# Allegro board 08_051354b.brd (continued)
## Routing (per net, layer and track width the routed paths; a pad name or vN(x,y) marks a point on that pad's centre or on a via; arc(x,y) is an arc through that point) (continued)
UNNAMED_5_ADP5023_I567_FB1: length 4.7
  TOP w0.305: v1(17.57,10.92) 17.57,9.97 17.7,9.84 R30.1 R23.1
  BOTTOM w0.203: v1(17.57,10.92) 18.21,11.55 U3.11
UNNAMED_5_ADP5023_I567_FB2: length 7.6
  TOP w0.305: v1(20.83,11.23) 20.83,10.67 20.16,10 v1(20.16,8.58)
  BOTTOM w0.203: R21.1 R20.1 19.35,8.17 19.75,8.58 v1(20.16,8.58)
  BOTTOM w0.305: v1(20.83,11.23) 20.06,11.23 19.71,11.58 U3.8
UNNAMED_5_ADP5023_I567_FB3: length 6.6
  TOP w0.203: v1(17.45,17.14) 17.09,16.79 14.38,16.79 14.01,17.15 R19.1 R18.2
  BOTTOM w0.254: v1(17.45,17.14) 17.71,16.88 U3.19
UNNAMED_5_ADP5023_I567_MODE: length 3.2
  BOTTOM w0.203: U3.13 16.38,12.91 15.54,12.06 15.54,10.79 JP4.2
UNNAMED_5_ADP5023_I567_SW1: length 4.5
  BOTTOM w0.254: 12.53,13.92 15.1,13.92 15.15,13.97 15.24,13.97 15.75,13.97 15.81,13.91 U3.15
UNNAMED_5_ADP5023_I567_SW2: length 3.6
  BOTTOM w0.254: U3.4 24.57,13.91
UNNAMED_5_ADP5023_I567_VOUT1: length 9.4
  TOP w0.508: R22.1 20.06,7.4 18.95,8.51 v1(18.63,8.51) 18.02,7.91 R30.2
  BOTTOM w0.254: 18.71,10.83 18.72,10.84 ; 18.71,10.83 U3.10 ; 18.71,10.83 18.41,10.54
UNNAMED_5_ADP5023_I567_VOUT2: length 13.1
  BOTTOM w0.305: U3.9 19.21,10.05 19.6,9.65 ; 26.44,10.18 26.44,10.27 C47.1 26.5,10.25 26.44,10.18 ; 26.44,10.18 26.44,9.14 26.14,8.84 23.83,8.84 23.37,8.38 23.37,7.75 22.11,6.48 R21.2 20.49,5.34 R32.1
UNNAMED_5_ADP5023_I567_VOUT3: length 1.2
  BOTTOM w0.254: U3.20 18.21,17.35
  vias: v1(17.11,17.97) v1(17.79,17.97)
UNNAMED_5_ADP5071_I420_COMP1: length 2.1
  TOP w0.203: R50.1 26.54,24.38 25.89,23.73 U10.6
UNNAMED_5_ADP5071_I420_COMP2: length 1.9
  TOP w0.203: R51.1 23.29,24.61 23.89,24 U10.10
UNNAMED_5_ADP5071_I420_EN1: length 6.1
  TOP w0.203: U10.7 25.39,24.18 25.7,24.49 25.7,25.51 v1(25.71,25.53)
  BOTTOM w0.203: JP7.2 23.29,25.26 24.04,26.01 25.22,26.01 25.7,25.53 v1(25.71,25.53)
UNNAMED_5_ADP5071_I420_EN2: length 10.3
  TOP w0.203: U10.9 24.39,24.04 25.19,24.84 25.19,26.24 25.77,26.82 29.23,26.82 v1(30.35,25.69)
  BOTTOM w0.203: v1(30.35,25.69) 30.35,25.65 30.39,25.62 JP6.2
UNNAMED_5_ADP5071_I420_FB1: length 4.6
  TOP w0.203: R48.1 29.89,23.38 ; 29.89,23.38 R52.1 ; 29.89,23.38 29.88,23.39 28.69,23.39 27.6,22.31 U10.5
UNNAMED_5_ADP5071_I420_FB2: length 6.2
  TOP w0.305: U10.11 21.55,22.31 21.13,22.73 21.13,24.01 20.23,24.9 R46.2 R49.1
UNNAMED_5_ADP5071_I420_INBK: length 4.4
  TOP w0.305: L9.1 30.84,20.87 30.28,20.31 U10.1
UNNAMED_5_ADP5071_I420_PVIN1: length 11.7
  TOP w0.254: 24.19,17.22 24.39,17.42 U10.17
  TOP w0.305: C41.1 23.89,16.24 U10.16 ; U10.15 21.92,20.31 20.42,18.82 20.42,16.89 20.68,16.64 21.21,16.64
UNNAMED_5_ADP5071_I420_SW2: length 1.5
  TOP w0.305: U10.18 24.89,17.83
UNNAMED_5_ADP5071_I420_SYNC: length 9.9
  TOP w0.203: U10.2 27.48,20.81 27.74,21.08 27.74,21.85 28.49,22.61 v1(31.82,22.61)
  BOTTOM w0.203: JP8.2 34.21,22.81 34.01,22.61 v1(31.82,22.61)
UNNAMED_5_ADP5071_I420_VREF: length 6.4
  TOP w0.305: R46.1 19.23,24.99 20.15,24.07 C43.1 20.32,22.46 20.38,22.46 21.05,21.79 22.86,21.79 U10.12
UNNAMED_5_ADP5071_I420_VREG: length 3
  TOP w0.305: U10.14 22.86,20.79 21.6,20.79 20.85,20.04 C66.1
UNNAMED_5_ADP7112_I458_EN: length 4.2
  TOP w0.203: U12.C1 102.12,10.61 v1(102.12,11.18)
  BOTTOM w0.203: R38.1 102.13,11.18 v1(102.12,11.18) 101.61,10.67 JP9.2
UNNAMED_5_ADP7112_I458_SENSE: length 5.4
  TOP w0.203: 100.98,10.24 101.18,10.03 U12.B2
  TOP w0.305: R57.1 97.51,9.84 R58.1 97.97,10.29 100.93,10.29 100.98,10.24
UNNAMED_5_ADP7112_I458_SS: length 2.7
  TOP w0.203: U12.B1 102.5,10.03 102.88,10.41 v1(103.52,10.41)
  BOTTOM w0.203: v1(103.52,10.41) 103.78,10.68 C80.1
UNNAMED_5_ADP7112_I458_VIN: length 4.1
  TOP w0.203: U12.A1 102.38,9.2
  TOP w0.508: 102.67,8.89 C79.1 104.03,7.73 ; R56.2 106.06,8.09
UNNAMED_5_ADP7112_I458_VOUT: length 6.1
  TOP w0.203: U12.A2 101.18,9.27
  TOP w0.508: C81.1 99.45,7.75 ; C81.1 100.81,8.89 ; C81.1 97.58,8.89 R58.2 97.51,7.82 R59.1
UNNAMED_5_CAP_I499_N1: length 21.5
  TOP w0.305: R49.2 18.47,26.67 18.16,26.37 v1(18.16,25.15)
  L3_SIG w0.305: v1(21.46,8.76) 21.05,8.76 20.24,9.57 20.24,15.77 21.05,16.58 21.05,23.02 18.92,25.15 v1(18.16,25.15)
UNNAMED_5_CAP_I500_N1: length 17
  TOP w0.203: R52.2 v1(31.8,23.37)
  TOP w0.508: 32.01,13.21 32.51,13.21 33.02,12.7 v1(33.02,11.69)
  L3_SIG w0.305: v1(31.8,23.37) 31.92,23.37 34.97,20.32 34.97,13.64 v1(33.02,11.69)
UNNAMED_5_CAP_I511_N1: length 16.4
  BOTTOM w0.508: 8.47,28.3 C42.1 ; C42.1 9.86,27.4 ; C42.1 9.86,29.2 ; C42.1 11.24,28.3 ; 7.27,28.62 E2.1 ; E2.1 7.27,30.78 ; E2.1 8.22,29.7 ; R100.2 8.02,32.14 ; R100.2 7.27,31.29 ; R100.2 7.27,32.99 ; S2.2 14.28,26.54 ; S2.2 11.12,26.54 ; S2.2 12.7,28.12 ; S2.2 12.7,24.97
UNNAMED_5_CAP_I516_N1: length 1.1
  TOP w0.203: R50.2 C72.1
UNNAMED_5_CAP_I517_N1: length 1.1
  TOP w0.305: R51.2 C74.1
UNNAMED_5_CN4PV6_I401_N1: length 21.8
  TOP w0.508: 3.06,3.63 P31.1B ; P31.1B 4.62,5.38 ; P31.1B 3.06,7.13 ; D1.C 7.23,19.06 ; D1.C 8.48,17.62 ; D1.C 5.99,17.62 ; D1.C 7.23,16.18 ; 3.06,9.73 P31.1A ; P31.1A 4.62,11.48 ; P31.1A 3.06,13.23 ; 12.7,20.27 S2.1 ; S2.1 11.12,21.84 ; S2.1 12.7,23.42 ; S2.1 14.28,21.84
UNNAMED_5_DIOLED_I652_P: length 5.7
  TOP w0.508: DS1.A 7.81,34.66 v1(6.77,34.66)
  BOTTOM w0.508: v1(6.77,34.66) 5.57,33.46 R100.1
UNNAMED_5_DIOLED_I662_P: length 2.4
  TOP w0.508: DS2.A v1(7.8,39.12)
  BOTTOM w0.508: R104.2 v1(7.8,39.12)
UNNAMED_5_DIOLED_I665_P: length 2.7
  TOP w0.508: DS3.A v1(7.67,42.42)
  BOTTOM w0.508: R108.1 v1(7.67,42.42)
UNNAMED_7_ADA4800PRELIM_I10_IDR: length 3.1
  TOP w0.203: C65.1 R33.1 111.55,20.45 111.55,21.08 112.21,21.73 A1.4
UNNAMED_7_ADA4800PRELIM_I10_IN: length 13.2
  TOP w0.203: U1.21 99.73,20.56 102.28,23.11 109.73,23.11 109.86,22.98 A1.1
UNNAMED_7_ADA4800PRELIM_I10_ISF: length 3.7
  TOP w0.203: A1.6 112.82,22.98 113.47,23.63 R31.1 C29.2
UNNAMED_7_ADA4800PRELIM_I10_OUT: length 1.6
  TOP w0.254: A1.3 109.75,21.98 109.48,21.71 R76.1
UNNAMED_7_ADA4800PRELIM_I10_VPO: length 2.9
  TOP w0.254: 112.97,22.34 112.97,21.48 112.56,21.07 R33.2 ; A1.5 113.03,22.48
UNNAMED_7_CAP_I99_N1: length 6.8
  BOTTOM w0.203: R27.1 C30.1 108.62,28.61 107.77,27.76 D5.A 108.38,27.15 108.82,26.72 Q1.3 109.56,26.72 109.73,26.54 109.73,26.16 109.58,26.02 Q1.1
UNNAMED_7_CAP_I107_N1: length 3.2
  BOTTOM w0.203: R7.2 C18.1 108.4,25.85 108.91,26.36 109.28,26.36 109.28,26.37 Q1.2
UNNAMED_7_CAP_I131_N1: length 2.1
  TOP w0.254: U1.30 99.21,26.78
  TOP w0.381: U1.30 v5(98.24,27.94)
  vias: v5(99.19,27.94)
UNNAMED_7_CAP_I133_N1: length 0.5
  BOTTOM w0.203: R69.2 C73.1
UNNAMED_7_CAP_I133_N2: length 5.2
  TOP w0.203: v1(97.2,21.86) U1.23
  BOTTOM w0.203: C73.2 96.38,25.08 97.2,24.26 v1(97.2,21.86)
UNNAMED_7_CAP_I142_N1: length 2
  TOP w0.406: U1.19 97.11,20.8 v1(96.57,21.34)
UNNAMED_7_CAP_I150_N1: length 3
  TOP w0.203: C21.1 110.49,19.38 JP5.1 R76.2
UNNAMED_7_ICFAN3121_I89_EN: length 11.3
  BOTTOM w0.203: JP2.2 95.63,12.32 98.11,14.8 102.35,14.8 102.66,15.11 102.66,15.78 102.46,15.98 U6.3
UNNAMED_7_ICFAN3121_I89_IN: length 4.2
  BOTTOM w0.203: U6.2 102.54,16.63 103.04,16.13 103.04,14.68 102.52,14.16 R5.2
UNNAMED_7_MN34906BL_I91_HL: length 7.1
  TOP w0.203: U1.17 v1(95.81,20.7)
  BOTTOM w0.203: R66.2 91.33,22.01 92.65,20.7 v1(95.81,20.7)
UNNAMED_7_RES_I93_N2: length 1.4
  BOTTOM w0.203: Q1.5 Q1.6 111.3,26.02 R26.2
UNNAMED_10_ADDI9036_I362_AUXINA: length 24.6
  TOP w0.203: RT1.2 69.06,32.62 R72.1 ; RT1.2 70.37,31.61 70.74,31.24 v1(71.37,31.24) ; RT1.2 70.65,32.9 R73.2 C57.2
  L2_GND w0.14: v4(74.4,22.91) 74.9,23.41 v2(74.9,23.41)
  L3_SIG w0.165: v1(71.37,31.24) 69.93,31.24 66.92,28.22 66.92,25.38 67.23,25.07 67.23,24.22 67.45,24 67.98,24 68.09,24.11 70.46,24.11 70.97,23.6 72.33,23.6 72.51,23.41 73.9,23.41 v4(74.4,22.91)
UNNAMED_10_ADDI9036_I362_DNC3: length 11.5
  TOP w0.14: 72.32,15.65 73.07,16.4 v2(73.07,18.71)
  TOP w0.203: 72.32,15.65 71.28,15.65 70.84,15.22 70.84,14.07 70.16,13.39 R89.1
  L2_GND w0.14: v2(73.07,18.71) 73.07,18.97 74.73,20.62 74.73,21.23 v2(74.9,21.41)
UNNAMED_10_ADDI9036_I362_DNC4: length 33
  L3_SIG w0.165: v1(68.24,20.32) 68.24,19.83 68.91,19.16 70.45,19.16 70.73,19.45 70.73,19.86 71.02,20.16 73.28,20.16 75.04,21.91 v4(75.4,21.91)
  L8_SIG w0.203: v1(64.52,28.7) 67.23,25.99 67.23,22.96 68.24,21.95 v1(68.24,20.32)
  BOTTOM w0.203: R88.1 75.64,26.25 75.44,26.45 75.44,27.94 74.81,28.57 73.53,28.57 73.28,28.32 69.23,28.32 68.85,28.7 v1(64.52,28.7)
UNNAMED_10_ADDI9036_I362_I2CSCL: length 20.5
  L3_SIG w0.165: v4(75.9,22.41) 75.9,23.08 75.56,23.42 75.56,27.26 75.4,27.42 73.76,27.42 73.17,28.02 70.79,28.02 v1(70.51,27.74)
  BOTTOM w0.203: v1(70.51,27.74) 70.51,26.7 70.94,26.26 71.53,26.26 71.83,25.96 71.83,23.37 73.57,21.63 R28.2 R41.2
UNNAMED_10_ADDI9036_I362_I2CSDA: length 7.9
  L3_SIG w0.122: 74.83,25.92 74.83,25.65 75.26,25.22 75.26,23.19 75.4,23.05 v4(75.4,22.41)
  L3_SIG w0.165: v3(74.83,26.44) 74.83,25.92
  BOTTOM w0.203: R6.2 R3.2 75.34,25.06 74.83,25.58 v3(74.83,26.44)
UNNAMED_10_ADDI9036_I362_MTEST: length 8.3
  L2_GND w0.14: 78.74,19.68 78.55,19.87 78.1,19.87 77.97,20 77.97,20.84 v2(77.4,21.41)
  L2_GND w0.203: v1(80.17,18.01) 78.91,19.27 78.91,19.51 78.74,19.68
  BOTTOM w0.203: R2.2 79.99,20.95 79.99,18.7 80.17,18.52 v1(80.17,18.01)
UNNAMED_10_FERRITE_I381_N1: length 5
  TOP w0.203: E1.1 66.41,27.21 C5.1 64.3,28.22 R1.2 63.65,26.95 Y1.4
UNNAMED_10_ICAT24CM01_I285_A2: length 3.7
  BOTTOM w0.203: U5.3 45.42,16.81 R47.1 R54.2
UNNAMED_10_ICAT24CM01_I285_WP: length 4.1
  BOTTOM w0.203: U5.7 46.07,26.75 R55.1 R60.2
UNNAMED_10_RES_I124_N1: length 1.6
  TOP w0.203: Y1.1 62.65,26.95 R1.1
UNNAMED_10_RES_I290_N1: length 3.5
  BOTTOM w0.203: R63.2 R62.1 46.25,17.02 46.07,17.21 U5.2
UNNAMED_10_RES_I374_N1: length 1.5
  TOP w0.203: R110.1 63.86,23.94 63.87,23.94 Y1.3
UNNAMED_12_ADT7410_I24_A0: length 4.4
  TOP w0.203: v1(92.22,10.54) 91.33,10.54 R106.2 91.07,10.54 U13.3
  BOTTOM w0.203: v1(92.22,10.54) 91.33,10.54 R106.2
UNNAMED_12_ADT7410_I24_A1: length 4.4
  TOP w0.203: U13.4 91.07,11.81 R103.2 91.33,11.81 v1(92.22,11.81)
  BOTTOM w0.203: R103.2 91.33,11.81 v1(92.22,11.81)
UNNAMED_12_CAP_I106_N2: length 7.5
  TOP w0.229: E5.2 76.94,7.96
  TOP w0.305: v1(73.66,9.47) 74.16,8.97 74.16,8.1 C1.2 74.86,7.6 75.54,8.27 C56.2 76.37,8.27 76.68,7.96 76.94,7.96
  BOTTOM w0.203: U7.10 73.86,9.97 73.66,9.78 v1(73.66,9.47)
UNNAMED_12_CN30PV2_I137_N13: length 13.4
  TOP w0.203: R98.2 v1(40.03,22.71) ; v1(48.48,26.61) 48.09,27 P1.13
  L3_SIG w0.165: v1(40.03,22.71) 40.74,22 42.13,22 47.12,26.98 47.92,26.98 47.94,26.96 48.13,26.96 v1(48.48,26.61)
UNNAMED_12_CN30PV2_I137_N14: length 13.1
  TOP w0.203: v1(40.95,22.73) 40.95,22.25 R109.2 ; v1(48.99,27.63) 48.61,28 P1.14
  L3_SIG w0.165: v1(48.99,27.63) 48.5,27.63 48.4,27.53 46.98,27.53 42.18,22.73 v1(40.95,22.73)
UNNAMED_12_CN30PV2_I137_N15: length 11.9
  TOP w0.508: v1(45.33,30.06) 45.33,29.3 45.63,29 P1.15
  L8_SIG w0.508: v1(49.66,23.31) 47.32,25.64 47.32,27.4 45.33,29.4 v1(45.33,30.06)
  BOTTOM w0.508: v1(49.66,23.31) 49.66,23.89 R35.2
UNNAMED_12_CN40PV2_I59_N15: length 89.9
  TOP w0.305: S3.2 38.64,3.98 38.04,4.58 C84.1 v1(36.96,5.71)
  L3_SIG w0.165: v1(67.55,39.24) 67.55,39.66 64.73,42.48 39.46,42.48 38.31,43.63 28.99,43.63 27.05,41.69 v1(27.05,41.4)
  L8_SIG w0.203: v1(27.05,41.4) 26.42,40.77 26.42,22.86 36.96,12.32 v1(36.96,5.71)
  BOTTOM w0.203: P4.29 v1(67.55,39.24)
UNNAMED_12_CN40PV2_I60_N14: length 89.6
  TOP w0.305: S4.1 41.24,3.98 41.85,4.58 C85.1 v1(42.67,5.71)
  L3_SIG w0.165: v1(28.11,41.23) 30.04,43.16 37.75,43.16 38.92,41.99 63.96,41.99 65.55,40.39 v1(65.55,39.88)
  L8_SIG w0.203: v1(42.67,5.71) 42.9,5.71 43.1,5.92 43.1,6.69 42.68,7.11 40.77,7.11 37.85,10.03 37.85,12.53 27.05,23.32 27.05,40.17 v1(28.11,41.23)
  BOTTOM w0.203: P4.28 v1(65.55,39.88)
UNNAMED_12_CN60PODDEVEN_I121_N5: length 2.5
  TOP w0.203: R113.2 53.43,3.8 v1(53.89,4.26)
  BOTTOM w0.203: v1(53.89,4.26) P3.9
UNNAMED_12_DIOLED_I181_N: length 55
  TOP w0.203: DS4.C v1(38.9,6.44) ; v1(14.82,39.5) 14.88,39.56 Q2.6
  L8_SIG w0.203: v1(14.82,39.5) 14.82,39.12 14.82,35.85 17.53,33.15 17.53,25.04 21.34,21.23 21.34,17.27 24.77,13.84 24.77,9.14 29.84,4.06 30.63,4.06 31.15,3.54 31.58,3.54 32.11,4.06 37.97,4.06 38.9,4.99 v1(38.9,6.44)
UNNAMED_12_DIOLED_I181_P: length 1.7
  TOP w0.305: R37.1 37.3,9.09 DS4.A
UNNAMED_12_DIOLED_I182_N: length 54.4
  TOP w0.203: DS5.C v1(42.58,6.48) ; Q2.3 v1(18.03,37.66)
  L8_SIG w0.203: v1(42.58,6.48) 40.39,6.48 39.75,7.11 38.35,7.11 37.85,6.6 37.85,5.46 37.21,4.83 30.35,4.83 25.53,9.65 25.53,17.88 18.68,24.73 18.68,33.01 17.65,34.04 17.65,37.28 v1(18.03,37.66)
UNNAMED_12_DIOLED_I182_P: length 1.7
  TOP w0.305: DS5.A 40.98,9.09 R75.2
UNNAMED_12_ICFSA642_I1_OEN: length 2.4
  BOTTOM w0.203: R90.2 76.04,10.11 75.92,9.99 74.92,9.99 74.65,10.25 U7.8
UNNAMED_12_ICFSA642_I1_SEL: length 103.4
  TOP w0.203: v1(5.88,38.52) S1.2
  L3_SIG w0.305: v1(5.88,38.52) 8.72,35.68 8.72,28.19 14.34,22.57 14.34,11.72 20.03,6.04 28.79,6.04 30.1,4.73 35.08,4.73 38.73,8.38 50.42,8.38 51.94,9.91 60.07,9.91 62.1,11.94 65.08,11.94 65.38,11.63 65.38,10.32 65.02,9.96 65.02,7.88 65.43,7.47 72.38,7.47 72.87,7.97 72.87,9.31 v1(72.99,9.42)
  BOTTOM w0.203: v1(72.99,9.42) 73.05,9.48 73.05,9.79 73.46,10.2 U7.11
UNNAMED_12_ICPCA9517A_I144_EN: length 2.7
  TOP w0.203: R101.1 88.66,38.1 87.86,38.9 U8.5
UNNAMED_12_ICPCA9517A_I145_EN: length 3.6
  BOTTOM w0.203: R24.2 76.34,33.78 75.79,33.23 U9.5
UNNAMED_12_RES_I54_N1: length 2.9
  TOP w0.203: S1.1 2.92,41.27 3.13,41.49 R91.1
UNNAMED_12_RES_I55_N2: length 2.1
  TOP w0.203: R36.2 2.29,37.47 S1.3
UNNAMED_12_RES_I155_N2: length 2.1
  TOP w0.508: S3.1 32.74,2.42 R77.2
UNNAMED_12_RES_I158_N2: length 2.1
  TOP w0.508: S4.2 47.14,2.42 R80.2
UNNAMED_12_RES_I178_N2: length 2.2
  TOP w0.203: R78.2 16.38,36.66 Q2.2
UNNAMED_12_RES_I179_N2: length 2
  TOP w0.203: R79.2 16.38,40.55 Q2.5
VD: length 59.1
  TOP w0.14: v1(77.82,15.54) 77.59,15.77 76.53,15.77 75.99,16.31 75.99,18.97 75.4,19.56 U4.F1
  TOP w0.203: TP1.1 47.29,39.95 47.77,39.95 47.8,39.91 53.59,39.91 53.9,39.6 v1(57.88,39.6)
  L8_SIG w0.165: v1(57.88,39.6) 60.72,36.76 63.04,36.76 64.65,35.15 64.65,31.75 63.5,30.6 63.5,27.05 64.65,25.9 64.65,22.97 65.03,22.59 65.03,21.18 66.21,20 67.85,20 68.03,19.82 68.45,19.82 68.83,20.2 76.33,20.2 78.21,18.31 78.21,15.94 v1(77.82,15.54)
VL: length 1.2
  TOP w0.508: R10.1 83.53,28.48 v1(84.15,28.48)
  vias: v5(27.14,3.11) v5(27.52,2.35) v5(28.32,3.08) v5(28.92,2.35) v5(29.43,3.11) v5(102.87,36.32) v5(102.87,35.43)
VL_AFE: length 7
  TOP w0.203: 77.6,25.91 77.4,25.71 U4.K11
  TOP w0.305: 77.6,25.91 78.03,26.34 79.52,26.34 79.71,26.53 C27.1
  TOP w0.508: C27.1 81.36,26.53 C20.2 81.44,26.81 R10.2
VLD: length 19.1
  TOP w0.254: P21.12 59.41,27.67 ; P21.10 59.41,28.17 ; P21.14 59.41,27.17 ; P21.18 59.41,26.17 ; P21.22 59.41,25.17 ; P21.8 59.41,28.67 ; P21.4 59.41,29.67 ; P21.2 59.41,30.18 ; P21.6 59.41,29.17 ; P21.16 59.41,26.67 ; P21.20 59.41,25.67 ; P21.24 59.41,24.67
  BOTTOM w0.508: R108.2 v1(10.76,41.27)
  vias: v1(59.56,30.1) v1(59.56,28.57) v1(59.56,27.81) v1(59.56,27.05) v1(59.56,26.29) v1(59.65,29.34) v1(59.75,25.07) v1(60.24,27.12) v1(60.33,29.21) v5(29.97,33.02) v5(29.97,32.13) v5(30.78,33.02) v5(30.78,32.13) v5(31.62,33.02) v5(31.62,32.13) v5(31.62,31.29) v5(31.62,30.48) v5(32.44,33.02) v5(32.44,32.13) v5(32.44,31.29) v5(32.44,30.48) v5(36.56,32.61) v5(36.56,31.6) v5(37.45,32.61) v5(37.45,31.6) v5(38.27,32.64) v5(38.27,31.62) v5(39.12,32.64) v5(39.12,31.62)
VSUB: length 8.3
  TOP w0.508: v5(106.06,11.56) R56.1
  BOTTOM w0.305: U6.8 98.49,17.28 98.07,17.7 v5(98.07,17.89)
  BOTTOM w0.381: v1(101.22,12.57) 100.71,12.57 100.31,12.17 100.31,10.82 100.78,10.35 JP9.1
  BOTTOM w0.508: JP2.1 v5(94.79,12.06)
  vias: v5(29.72,8.13) v5(29.72,6.86) v5(30.61,8.13) v5(30.61,6.86) v5(104.52,14.35) v5(104.57,17.68) v5(105.54,14.61) v5(105.58,20.73) v5(105.58,19.71) v5(105.58,18.69) v5(105.58,17.68) v5(105.58,16.66) v5(105.58,15.65)

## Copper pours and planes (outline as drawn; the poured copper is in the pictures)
5V_LD on TOP: 50.16,20.45 50.16,23.88 50.85,23.88 50.85,23.8 52.18,23.8 52.31,23.67 52.18,23.54 50.85,23.54 50.85,23.3 52.18,23.3 52.31,23.17 52.18,23.04 50.85,23.04 50.85,22.8 52.18,22.8 52.31,22.67 52.18,22.54 50.85,22.54 50.85,22.3 52.18,22.3 52.31,22.17 52.18,22.04 50.85,22.04 50.85,21.8 52.18,21.8 52.31,21.67 52.18,21.54 50.85,21.54 50.85,21.3 52.18,21.3 52.31,21.17 52.18,21.04 50.85,21.04 50.85,20.79 52.18,20.79 52.31,20.67 52.18,20.54 50.85,20.54 50.85,20.45
5V_LD on BOTTOM: 7.46,23.69 7.11,23.37 7.11,21.34 7.33,21.15 9.49,21.15 10,21.66 10,23.43 9.74,23.69
5V_LD on BOTTOM: 16.91,29.84 16.91,31.78 16.4,32.28 14.67,32.28 14.42,32.03 14.42,30.02 14.6,29.84
5V_LD on BOTTOM: 34.87,27.71 34.87,25.32 39.8,25.32 39.8,27.71
5V_LD on L5_PWR: 1.27,17.08 1.27,34.35 26.41,34.35 28,32.76 28,29.97 29.33,28.64 51.18,28.64 52.01,27.81 52.01,20.58 51.43,20 21.21,20 20.51,20.71 20.51,23.63 18.8,25.34 14.09,25.34 12.13,23.37 12.13,20.2 9.01,17.08
5VCC on TOP: 21.81,17.85 20.92,17.85 20.92,18.74 22.06,19.88 23.33,19.88 23.46,19.75 23.46,18.74 23.2,18.35 21.93,18.35 21.81,18.23
5VCC on BOTTOM: 26.25,20.01 26.38,19.88 26.38,18.74 26.25,18.61 23.46,18.61 23.33,18.48 22.32,18.48 22.19,18.61 22.19,19.88 22.32,20.01
5VCC on BOTTOM: 6.17,28.91 6.19,28.9 6.19,30.93 5.93,31.18 3.52,31.18 3.27,30.93 3.27,29.15 2.88,28.77 1.61,28.77 1.36,28.51 1.36,26.48 1.61,26.23 3.65,26.23 4.03,26.61 5.81,26.61 5.93,26.74 5.93,28.65
5VCC on BOTTOM: 21.64,22.61 21.51,22.73 21.51,23.24 21.64,23.37 23.29,23.37 23.41,23.24 23.41,22.73 23.29,22.61
5VCC on L6_PWR: 1.27,1.27 1.27,32.96 25.14,32.96 32.25,25.84 40.38,25.84 40.83,25.4 40.83,14.22 42.99,12.06 42.99,6.74 41.91,5.65 30.6,5.65 29.4,4.45 29.4,1.27 ; 1 cut-out
9VDD on TOP: 94.95,7.29 96.88,7.29 96.88,8.26 95.38,8.26 94.66,8.97 93.05,8.97 93.05,7.45 94.78,7.45
9VDD on L6_PWR: 93.66,7.27 93.66,21.34 91.06,23.94 82.05,23.94 81.34,24.64 81.34,26.03 83.32,28 125.59,28 125.59,7.27
GND on TOP: 67.65,25.21 70.19,25.21 70.45,24.96 70.45,23.43 69.81,22.8 69.69,22.8 69.56,22.67 69.56,17.47 66.64,14.54 59.65,14.54 59.23,14.97 59.23,22.64 65.08,22.64 ; 1 cut-out
GND on TOP: 20.92,21.4 20.54,21.78 19.65,21.78 19.39,22.04 19.39,24.07 19.14,24.32 17.87,24.32 17.62,24.07 17.62,19.12 17.74,18.99 19.14,18.99 19.27,19.12 19.27,20.51 19.52,20.77 20.54,20.77 20.92,21.15
GND on TOP: 26.97,13.08 26.97,9.27 25.11,7.43 25.11,4 25.36,3.75 28.16,3.75 28.41,4 28.41,9.59 29.05,10.23 29.05,13.66 30.06,14.67 33.36,14.67 33.7,14.99 33.75,15.05 33.75,16.7 33.49,16.96 27.9,16.96 27.65,17.21 27.43,17.45 26.47,18.41 25.91,18.41 25.78,18.54 25.65,18.54 25.57,18.41 25.57,14.48
GND on TOP: 1.27,1.27 1.27,43.73 39.5,43.73 39.5,41.78 44.32,41.78 44.32,43.73 125.59,43.73 125.59,7.27 77.73,7.27 77.73,1.27 ; 27 cut-outs
GND on BOTTOM: 102.62,26.16 102.62,31.5 104.74,31.5 104.74,26.16
GND on BOTTOM: 106.26,14.16 106.26,21.28 106.43,21.44 106.43,22.1 108.97,22.1 109.22,21.84 109.22,21.25 109.18,21.21 109.18,14.16 108.61,13.59 106.44,13.59 106.44,13.98
GND on BOTTOM: 23.33,25.72 21.97,25.72 21.97,24.64 20.19,24.64 20.19,25.4 20.66,25.87 20.66,32.2 20.79,32.32 22.19,32.32 22.44,32.58 22.44,34.1 22.65,34.29 22.78,34.44 22.78,34.72 23.59,34.72 23.59,32.45 23.71,32.32 24.98,32.32 25.11,32.2 25.11,26.36 24.98,26.23 23.71,26.23
GND on BOTTOM: 12.75,13.59 16.18,13.59 16.18,13.23 16.07,13.23 15.92,13.08 15.92,12.95 15.03,12.06 12.62,12.06 12.49,12.19 12.49,13.34
GND on BOTTOM: 60.2,24.64 57.28,24.64 56.77,24.13 56.77,15.37 57.66,14.48 66.93,14.48 70.66,18.21 70.66,24.84 70.1,25.4 60.96,25.4
GND on BOTTOM: 21.52,21.15 21.93,20.74 21.93,15.43 21.3,14.8 20.54,14.8 20.41,14.93 20.41,15.43 20.16,15.69 19.65,15.69 19.65,16.83 19.9,17.08 20.16,17.08 20.54,17.47 20.54,19.62 20.16,20.01 16.47,20.01 16,19.55 16,17.79 17.24,16.58 17.24,15.69 17.36,15.56 17.36,15.31 16.6,15.31 16.47,15.43 16.47,16.07 15.33,17.21 13.75,17.21 13.45,16.91 13.34,17.02 13.34,17.4 13.97,18.03 14.19,18.03 14.19,20.01 15.33,21.15
GND on BOTTOM: 1.27,1.27 1.27,20.07 1.4,20.07 3.43,22.1 3.43,22.73 6.6,22.73 6.6,25.78 1.27,25.78 1.27,43.73 125.59,43.73 125.59,7.27 77.72,7.27 77.72,8.51 74.42,8.51 74.42,9.14 74.93,9.14 74.93,9.91 74.3,9.91 74.3,9.53 74.04,9.53 74.04,9.14 73.15,9.14 73.15,9.02 72.64,9.02 72.64,8.51 69.98,8.51 69.98,6.99 53.34,6.99 53.34,3.3 69.98,3.3 69.98,1.27 ; 29 cut-outs
GND on BOTTOM: 21.64,13.54 23.8,13.54 24.13,13.21 24.13,11.94 23.75,11.56 22.86,11.56 22.23,10.92 21.46,10.92 21.34,11.05 21.34,12.32 21.64,12.62
GND on BOTTOM: 3.9,25.59 3.9,23.88 4.15,23.62 6.6,23.62 6.73,23.5 6.73,20.7 4.32,20.7 2.92,22.1 2.92,22.35 2.47,22.8 1.74,22.8 1.36,23.18 1.36,25.72 1.49,25.85 3.65,25.85
GND on BOTTOM: 99.28,20.26 102.81,20.26 102.81,23.21 102.58,23.43 99.28,23.43 99.02,23.18 99.02,20.51
GND on L2_GND: 77.73,7.27 77.73,1.27 1.27,1.27 1.27,43.73 125.59,43.73 125.59,7.27 ; 2 cut-outs
GND on L3_SIG: 1.27,1.27 1.27,43.73 39.5,43.73 39.5,41.78 44.32,41.78 44.32,43.73 125.59,43.73 125.59,7.27 77.73,7.27 77.73,1.27 ; 10 cut-outs
GND on L4_GND, L9_GND: 77.73,1.27 1.27,1.27 1.27,43.73 125.59,43.73 125.59,7.27 77.73,7.27
GND on L7_GND: 77.73,7.29 77.73,1.27 1.27,1.27 1.27,43.71 125.59,43.71 125.59,7.29
GND on L8_SIG: 60.86,40.24 61.01,40.18 61.16,40.25 61.17,40.27 64.29,43.38 64.34,43.59 64.18,43.73 125.59,43.73 125.59,7.27 77.73,7.27 77.73,1.27 1.27,1.27 1.27,43.73 39.5,43.73 39.5,41.78 44.32,41.78 44.32,43.73 45.78,43.73 45.61,43.59 45.66,43.38 46.6,42.44 46.6,40.98 46.73,40.8 46.95,40.84 48.3,42.18 58.7,42.18 58.91,42.14 59.08,42.03 ; 28 cut-outs
1P8VDD on TOP: 16.85,24.32 15.46,24.32 15.2,24.07 15.2,22.55 15.46,22.29 16.85,22.29 17.11,22.55 17.11,24.07
1P8VDD on L5_PWR: 1.27,1.27 1.27,16.45 9.28,16.45 12.76,19.93 12.76,23.11 14.36,24.7 18.54,24.7 19.88,23.36 19.88,19.82 16.95,16.9 16.95,11.93 18.16,10.73 23.75,10.73 25.21,12.19 25.21,18.66 25.91,19.37 51.69,19.37 52.64,20.32 52.64,23.11 53.22,23.69 62.87,23.69 65.85,26.67 65.85,43.73 78.93,43.73 78.93,28.7 80.39,27.24 91.82,27.24 93.03,26.03 93.03,16.51 92.45,15.94 57.4,15.94 55.88,14.41 32.25,14.41 28,10.16 28,6.1 25.59,3.69 25.59,1.27
2P1VDD on BOTTOM: 17.57,3.68 17.32,3.94 17.32,5.59 17.45,5.71 19.22,5.71 19.48,5.46 19.48,4.19 18.97,3.68
2P1VDD on BOTTOM: 18.59,16.84 18.59,19.56 18.72,19.68 20.11,19.68 20.37,19.43 20.37,17.91 20.11,17.53 19.1,17.53 18.84,17.27 18.84,16.84
2P1VDD on L8_SIG: 17.56,3.78 20.34,3.78 20.72,4.17 20.72,18.18 20.42,18.48 18.74,18.48 18.5,18.23 18.5,17.63 17.16,16.29 17.16,4.18
3P3VDD on L6_PWR: 71.18,1.27 71.18,8.12 75.32,12.26 84.46,12.26 86.17,13.97 86.17,20.2 85.09,21.27 77.85,21.27 74.8,18.22 72.26,18.22 70.48,16.45 67.06,16.45 66.36,17.15 66.36,27.3 74.55,35.5 79.89,35.5 80.96,36.57 80.96,41.41 80.27,42.1 71.5,42.1 62.86,33.46 54.86,33.46 53.66,32.26 53.66,25.53 52.57,24.45 50.17,24.45 50.1,24.52 50.1,25.01 50.86,25.78 50.86,26.93 49.21,28.58 49.21,29.98 47.76,31.43 42.54,31.43 40.83,29.72 40.83,26.93 40.38,26.48 32.52,26.48 25.4,33.59 1.27,33.59 1.27,43.73 125.59,43.73 125.59,28.64 83.05,28.64 80.71,26.29 80.71,24.38 81.78,23.3 90.8,23.3 93.03,21.08 93.03,7.27 77.73,7.27 77.73,1.27
IOVDD on L6_PWR: 30.04,1.27 30.04,4.19 30.87,5.02 42.17,5.02 43.62,6.47 43.62,12.32 41.47,14.48 41.47,29.46 42.8,30.8 47.49,30.8 48.58,29.71 48.58,28.32 50.23,26.67 50.23,26.04 49.47,25.28 49.47,24.25 49.91,23.81 52.84,23.81 54.29,25.27 54.29,32 55.12,32.83 63.12,32.83 71.76,41.47 80.01,41.47 80.33,41.14 80.33,36.83 79.62,36.13 74.29,36.13 65.72,27.56 65.72,16.89 66.8,15.81 70.74,15.81 72.52,17.59 75.06,17.59 78.11,20.64 84.83,20.64 85.53,19.93 85.53,14.23 84.2,12.89 75.05,12.89 70.55,8.39 70.55,1.27
UNNAMED_5_ADP2505V2_I467_SWA1 on BOTTOM: 22.78,39.5 22.65,39.37 20.75,39.37 20.49,39.12 20.49,36.96 21.64,35.81 22.53,35.81 22.53,35.56 19.1,35.56 18.97,35.69 18.97,43.56 19.04,43.63 22.7,43.63 22.78,43.54
UNNAMED_5_ADP2505V2_I467_SWB1 on BOTTOM: 24.05,43.58 24.05,39.62 24.18,39.5 25.95,39.5 26.34,39.12 26.34,36.2 25.57,35.31 24.73,35.31 24.73,35.08 26.87,35.08 27.61,35.81 27.61,43.56 27.53,43.64 27.52,43.63 24.09,43.63
UNNAMED_5_ADP2505V2_I467_VIN1 on BOTTOM: 21.78,32.71 19.9,32.71 19.65,32.45 19.65,25.85 19.39,25.59 15.33,25.59 15.08,25.85 15.08,28.13 15.33,28.39 16.47,28.39 17.36,29.28 17.36,34.74 17.87,35.25 22.44,35.25 22.44,34.63 21.97,34.16 21.97,32.89
UNNAMED_5_ADP2505V2_I467_VOUT1 on BOTTOM: 29.05,29.91 29.05,34.36 28.55,34.85 23.84,34.85 23.84,32.96 23.97,32.83 26.63,32.83 26.76,32.71 26.76,26.23 26.89,26.1 30.82,26.1 31.21,26.48 31.21,29.4 30.95,29.66 29.3,29.66
UNNAMED_5_ADP5023_I567_AVIN on BOTTOM: 16.21,14.56 16.1,14.56 14.91,15.75 13,15.75 12.87,15.62 12.87,14.48 13.13,14.22 16.21,14.22
UNNAMED_5_ADP5023_I567_AVIN on BOTTOM: 16.3,15.11 16.3,15.88 15.29,16.89 14.27,16.89 14.14,16.76 14.14,16.13 14.27,16 15.04,16 15.93,15.11
UNNAMED_5_ADP5023_I567_AVIN on BOTTOM: 22.05,14.22 22.02,14.25 21.72,14.25 21.72,14.86 22.19,15.33 22.19,18.1 22.32,18.23 23.59,18.23 24.22,17.59 27.14,17.59 27.27,17.47 27.27,15.81 27.14,15.69 24.6,15.69 24.36,15.42 24.34,15.42 24.09,15.18 24.09,14.22
UNNAMED_5_ADP5023_I567_AVIN on L5_PWR: 18.42,11.37 17.59,12.2 17.59,16.63 20.32,19.37 23.94,19.37 23.94,19.3 24.57,18.66 24.57,12.45 23.49,11.37
UNNAMED_5_ADP5023_I567_AVIN on L6_PWR: 15.88,11.62 14.92,12.58 14.92,16.38 15.63,17.08 18.67,17.08 20.07,18.48 23.74,18.48 24.19,18.03 24.19,12.45 23.36,11.62
UNNAMED_5_ADP5023_I567_SW1 on BOTTOM: 12.49,14.99 12.49,14.35 12.87,13.97 16.68,13.97 16.68,13.84 16.56,13.72 12.49,13.72 12.24,13.46 9.57,13.46 9.44,13.59 9.44,14.99 9.57,15.11 12.37,15.11
UNNAMED_5_ADP5023_I567_SW2 on BOTTOM: 24.35,13.78 24.26,13.78 24.26,14.04 24.35,14.04 24.6,14.29 24.6,14.93 24.73,15.05 27.27,15.05 27.4,14.93 27.4,13.66 27.27,13.53 24.6,13.53
UNNAMED_5_ADP5023_I567_VOUT1 on BOTTOM: 12.11,9.14 12.11,7.75 12.24,7.62 18.31,7.62 18.84,8.15 18.84,9.91 18.85,9.96 18.84,10.16 18.85,10.95 18.85,11.43 18.59,11.43 18.59,11.3 16.81,9.53 14.14,9.53 12.24,11.43 12.24,13.08 12.11,13.21 9.57,13.21 9.44,13.08 9.44,11.81
UNNAMED_5_ADP5023_I567_VOUT2 on BOTTOM: 19.08,11.43 19.08,10.01 19.77,9.34 27.78,9.34 27.9,9.46 27.9,12.89 27.78,13.15 24.98,13.15 24.81,12.95 24.81,11.43 24.56,11.18 23.16,11.18 22.53,10.54 20.32,10.54 19.43,11.43
UNNAMED_5_ADP5023_I567_VOUT3 on TOP: 16.98,17.59 18.25,17.59 18.38,17.72 18.38,18.48 18.25,18.61 17.62,18.61 17.11,19.12 17.11,21.78 16.98,21.91 15.33,21.91 15.2,21.78 15.2,20.51 15.46,20.26 15.71,20.26 15.84,20.13 15.84,18.61 15.46,18.23 14.7,18.23 14.7,17.47 14.95,17.21 16.6,17.21
UNNAMED_5_ADP5023_I567_VOUT3 on BOTTOM: 18.33,16.84 18.33,19.56 18.21,19.68 16.81,19.68 16.68,19.56 16.68,17.78 16.81,17.65 17.7,17.65 18.08,17.27 18.08,16.84
UNNAMED_5_ADP5071_I420_INBK on TOP: 27.84,20.45 28.16,20.77 28.16,21.66 28.54,22.04 32.98,22.04 33.24,21.78 33.24,20.13 32.98,19.88 27.99,19.88 27.69,20.2 27.69,20.41 27.72,20.45
UNNAMED_5_ADP5071_I420_PVIN1 on TOP: 21.93,17.34 24.22,17.34 24.35,17.21 24.35,14.42 21.05,14.42 20.92,14.54 20.92,17.47 21.05,17.59 21.68,17.59
UNNAMED_5_ADP5071_I420_SW1 on TOP: 25.76,18.97 25.76,19.68 25.81,19.74 27.43,19.74 28.09,19.08 33.09,19.08 33.57,19.56 36.88,19.56 37,19.43 37,17.53 36.88,17.4 28.4,17.4 27.05,18.75 25.98,18.75
UNNAMED_5_ADP5071_I420_SW2 on TOP: 26.51,13.02 26.51,9.85 26.25,9.59 24.35,9.59 23.71,10.23 22.32,10.23 22.19,10.35 22.19,13.66 22.44,13.91 24.22,13.91 24.73,14.42 24.73,18.48 25.24,18.48 25.24,14.29
UNNAMED_5_ADP7112_I458_VIN on TOP: 106.77,8.83 105.75,8.83 105.12,9.59 102.51,9.59 101.9,8.99 101.9,7.47 102.07,7.31 106.9,7.31 107.02,7.43 107.02,8.58
UNNAMED_5_ADP7112_I458_VOUT on TOP: 97.5,8.45 97.76,8.45 98.77,9.46 101.13,9.46 101.57,9.02 101.57,7.57 101.29,7.29 97.26,7.29 97.26,8.21
UNNAMED_5_CAP_I59_N2 on BOTTOM: 4.47,25.95 4.47,24.21 4.64,24.05 7.08,24.05 7.35,24.32 9.74,24.32 10,24.58 10,25.81 9.7,26.1 8.13,26.1 7.78,26.45 7.78,27.42 7.57,27.63 6.45,27.63 6.27,27.45 6.27,26.27 6.13,26.13 4.66,26.13
UNNAMED_5_CAP_I499_N1 on TOP: 21,9.4 23.67,9.4 24.05,9.14 24.05,4.57 23.29,3.81 23.29,2.29 22.02,2.29 21.76,2.54 21.76,7.11 20.75,8.13 20.75,9.14
UNNAMED_5_CAP_I500_N1 on TOP: 36.92,16.83 37.05,16.7 37.05,12.39 36.79,12.26 32.35,12.26 31.21,11.12 31.21,9.85 31.08,9.72 29.94,9.72 29.81,9.85 29.81,13.53 30.32,14.16 33.62,14.16 34.38,14.93 34.38,16.7 34.51,16.83
UNNAMED_5_CAP_I511_N1 on BOTTOM: 14.19,24.58 14.57,24.96 14.57,29.02 14.06,29.53 12.03,29.53 11.52,30.04 9.23,30.04 8.35,30.93 8.35,33.21 8.22,33.34 6.82,33.34 6.69,33.21 6.69,28.26 6.82,28.13 7.71,28.13 8.09,27.75 8.09,26.99 8.47,26.61 9.74,26.61 10.38,25.97 10.38,24.96 10.76,24.58
UNNAMED_5_CN4PV6_I401_N1 on TOP: 1.36,3.08 1.97,2.48 5.93,2.48 6.19,2.73 6.19,12.13 8.98,14.93 8.98,18.23 10.38,19.62 13.81,19.62 14.57,20.39 14.57,24.07 14.31,24.32 10.63,24.32 10.38,24.07 10.38,21.78 9.36,20.77 6.06,20.77 5.04,19.75 5.04,18.74 1.36,15.05
UNNAMED_5_FERRITE_I642_N2 on TOP: 25.65,3.17 25.65,2.41 25.4,2.16 23.88,2.16 23.62,2.41 23.62,3.17 23.88,3.43 25.4,3.43
UNNAMED_7_ADA4800PRELIM_I10_VPO on TOP: 112.84,22.04 116.42,22.04 116.68,22.29 116.68,24.83 116.49,25.02 114.32,25.02 114.09,24.79 114.09,23.62 113.08,22.61 112.84,22.61
UNNAMED_7_CAP_I131_N1 on TOP: 97.63,26.23 97.63,28.39 97.75,28.51 100.17,28.51 100.29,28.39 100.29,26.48 100.04,26.23
UNNAMED_7_CAP_I131_N1 on BOTTOM: 96.23,28.13 96.23,26.86 96.86,26.23 101.18,26.23 101.44,26.48 101.44,32.83 100.93,33.34 100.93,34.23 101.44,34.74 101.44,36.52 101.31,36.64 99.28,36.64 99.15,36.52 99.15,31.05
UNNAMED_7_CAP_I138_N1 on BOTTOM (solid shape): 97.58,18.37 97.58,17.53 98.34,16.76 99.11,16.76 99.11,16 98.98,15.88 98.17,15.88 97.54,16.51 97.28,16.76 96.52,16.76 96.52,18.54 97.41,18.54
UNNAMED_7_CAP_I142_N1 on BOTTOM: 95.04,21.21 95.04,23.5 95.3,23.75 95.3,24.77 96.06,24.77 96.82,24 96.82,21.21 96.69,21.08 95.17,21.08
VL on TOP: 26,2.23 26,3.37 26.13,3.5 29.55,3.5 29.68,3.37 29.68,2.1 29.55,1.97 26.25,1.97
VL on BOTTOM: 101.69,35.25 101.69,36.52 101.82,36.64 102.96,36.64 103.21,36.39 103.21,35.25 103.09,35.12 101.82,35.12
VL on L5_PWR: 26.23,1.27 26.23,3.42 27.06,4.25 44.07,4.25 47.12,7.3 73.03,7.3 75.95,10.22 106.18,10.22 107.25,11.3 107.25,21.34 106.18,22.42 94.75,22.42 93.66,23.5 93.66,26.29 92.08,27.88 80.65,27.88 79.57,28.96 79.57,43.73 125.59,43.73 125.59,7.27 77.73,7.27 77.73,1.27
VLD on TOP: 56.9,31.11 56.9,24.51 60.58,24.51 60.58,31.11
VLD on BOTTOM: 32.71,30.04 29.68,30.04 29.43,30.29 29.43,33.36 29.72,33.66 39.57,33.66 39.83,33.4 39.83,29.92 39.62,29.72 33.03,29.72
VLD on L5_PWR: 53.22,24.32 52.64,24.9 52.64,28.07 51.44,29.27 29.6,29.27 28.64,30.23 28.64,33.02 26.67,34.99 1.27,34.99 1.27,43.73 65.21,43.73 65.21,26.93 62.61,24.32
VSUB on TOP: 30.91,6.6 30.78,6.48 29.38,6.48 29.26,6.6 29.26,9.02 29.53,9.29 30.8,9.29 30.91,9.19
VSUB on BOTTOM: 100.42,19.62 100.55,19.75 102.96,19.75 103.48,20.27 103.47,20.77 103.47,21.3 103.7,21.53 105.75,21.53 106.01,21.28 106.01,14.16 105.75,13.91 103.72,13.91 103.47,14.16 103.47,16.83 103.21,17.08 101.56,17.08 101.31,17.34 101.31,17.72 100.8,18.35 100.55,18.35 100.42,18.48
VSUB on L5_PWR: 29.85,4.89 28.64,6.1 28.64,9.9 32.52,13.78 56.14,13.78 57.66,15.3 92.71,15.3 93.66,16.25 93.66,20.57 94.87,21.78 105.91,21.78 106.62,21.08 106.62,11.56 105.91,10.86 75.69,10.86 72.77,7.94 46.86,7.94 43.81,4.89

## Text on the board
BOTTOM: SECONDARY SIDE | 08-051354 REV B Z
Ref Des/Silkscreen Bottom: A | C
User.Comments: 5.    SOLDER PIN 2 AND 3 OF JP3,JP5,JP6,JP7,JP8, AND JP9. | 6.    SOLDER PIN 1 AND 2 OF JP1,JP2, AND JP4.
Ref Des/Silkscreen Top: A | C | ADDI9035-36 | PRIMARY SIDE | 08-051354 REV B Z | 96TOF CAMERA1
DIMENSION: (REF) | DIA MAX | +2/-0 MILS | DESIGN CROSS SECTION CHART | TOTAL THICKNESS: 63 MILS | SILK/MASK_TOP | SILK/MASK_BOT | L2 L2_GND PLANE | L4 L4_GND PLANE | L5 L5_PWR PLANE | L6 L6_PWR PLANE | L7 L7_GND PLANE | L9 L9_GND PLANE | L1 TOP CONDUCTOR | L3 L3_SIG CONDUCTOR | L8 L8_SIG CONDUCTOR | L10 BOTTOM CONDUCTOR | 1-10 | 1-2 | 2-3 | 9-10
PAGE_OUTLINE: B | AS PER ECR-085792 & ECR-086716 | 20MAR19 | A.COZMA | MEZZANINE BOARD Z
User.8: L2 GND | 08-      -07
User.9: L3 SIG | 08-      -08
User.11: L4 GND | 08-      -09
User.12: 16.    BOARDS TO BE PANELIZED AND SHIPPED INTACT. | IMPEDANCE CONTROLLED LINES = 0.0065" ( L3 AND  L8) | CHARACTERISTIC IMPEDANCE = 50 OHMS +/- 10% | ARTWORK LINE WIDTH FOR | IMPEDANCE CONTROLLED LINES = 0.008" ( L1 AND  L10) | IMPEDANCE CONTROLLED SPACE = 0.007" | 0.00065" | 0.0013" | 0.002" | 0.00507" | 0.008" | 0.00733" | 0.003" | 0.0034" | 50 OHMS, | 100 OHMS | 2
User.15: L5 PWR | 08-      -10
User.16: L6 PWR | 08-      -11
User.17: L7 GND | 08-      -12
User.18: L8 SIG | 08-      -13
User.19: L9 GND | 08-      -14
User.20: L11 GROUND
User.21: L10 SIGNAL
User.22: L12 SIGNAL
User.23: L13 GROUND
User.29: 3 | DRILLED HOLES LAYER 2 TO LAYER 3 | DIA MAX | SEE NOTE 15
User.30: 4 | DRILLED HOLES LAYER 2 TO LAYER 5 | DIA MAX
User.31: 5 | DRILLED HOLES LAYER 2 TO LAYER 11 | DIA MAX | SEE NOTE 15
User.32: SECONDARY SIDE
User.45: DRILLED HOLES LAYER 9 TO LAYER 10 | FIGURE | SIZE | 8.0 | 10.0 | 12.0 | 70.0 | 31.0 | 40.0 | 40.16 | 47.0 | 57.09 | 59.0 | 63.0 | 71.0 | 98.0 | 120.0 | DRILL CHART: TOP to BOTTOM | FINISHED HOLES IN MILS | PLATED | NON-PLATED | QTY | 3 | 340 | 245 | 1 | 2 | 4 | TOLERANCE/NOTES | 5.0 | DRILL CHART: TOP to L2_GND | DRILL CHART: L2_GND to L3_SIG | DRILL CHART: L9_GND to BOTTOM | 76 | 35 | 8
